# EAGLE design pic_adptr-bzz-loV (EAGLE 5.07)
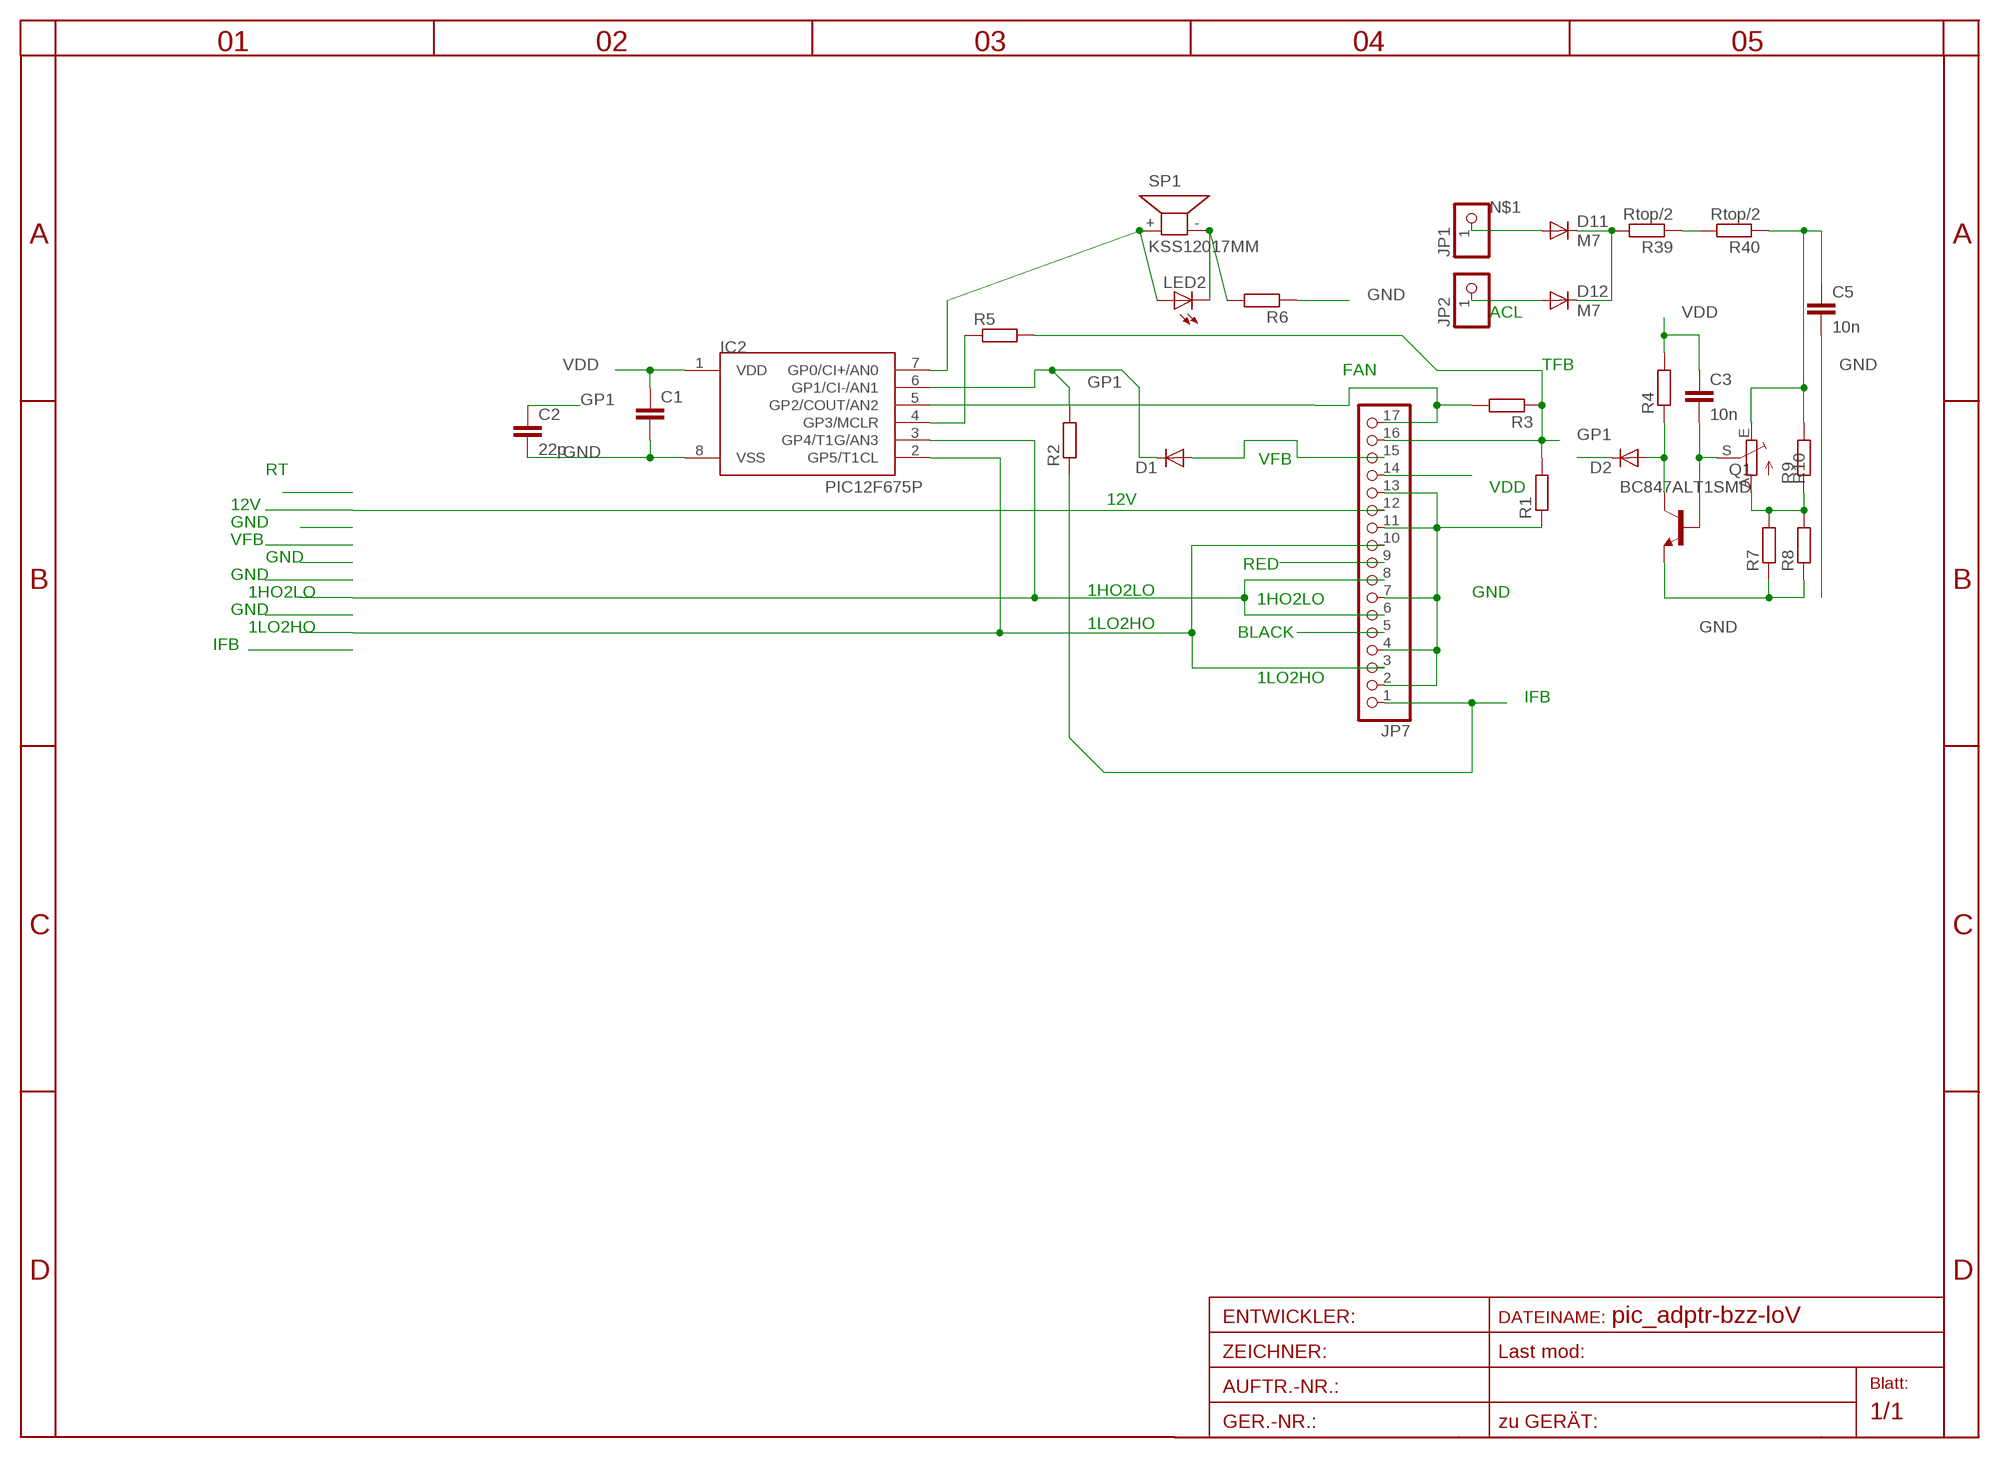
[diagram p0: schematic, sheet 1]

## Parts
C1  C-EUC1206  [C1206]
C2  22p  C-EUC0805  [C0805]
C3  10n  C-EUC0805  [C0805]
C5  10n  C-EUC1206  [C1206]
D1  DIODE-MINIMELF  [MINIMELF]
D2  DIODE-MINIMELF  [MINIMELF]
D11  M7  DIODE-SMA-DO214  [SMA-DO214AC]
D12  M7  DIODE-SMA-DO214  [SMA-DO214AC]
IC2  PIC12F675P  [DIL8]
JP1  PINHD-1X11X0.4  [1X01]
JP2  PINHD-1X11X0.4  [1X01]
JP7  PINHD-1X17  [1X17]
LED2  LEDCHIPLED_1206  [CHIPLED_1206]
Q1  BC847ALT1SMD  [SOT23]
R1  R-EU_R1206  [R1206]
R2  R-EU_R0805  [R0805]
R3  R-EU_R0805  [R0805]
R4  R-EU_R1206  [R1206]
R5  R-EU_R0805  [R0805]
R6  R-EU_R0805  [R0805]
R7  R-EU_R0805  [R0805]
R8  R-EU_R0805  [R0805]
R9  R-EU_R1206  [R1206]
R10  TRIM_EU-B64Y  [B64Y]
R39  Rtop/2  R-EU_R1206  [R1206]
R40  Rtop/2  R-EU_R1206  [R1206]
SP1  KSS12017MM  [KSS1202]

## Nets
1HO2LO: IC2.3(GP4/T1G/AN3) JP7.6 JP7.8
1LO2HO: IC2.2(GP5/T1CL) JP7.3 JP7.10
12V: JP7.12
ACL: D12.A JP2.1
BLACK: JP7.5
FAN: IC2.5(GP2/COUT/AN2) JP7.17 R3.2
GND: C1.2 C2.2 C5.2 IC2.8(VSS) JP7.2 JP7.4 JP7.7 JP7.11 JP7.13 Q1.2(E) R1.1 R6.1 R7.1 R8.1
GP1: C2.1 D1.C D2.C IC2.6(GP1/CI-/AN1) R2.2
IFB: JP7.1 R2.1
N$1: D11.A JP1.1
N$2: D11.K(C) D12.K(C) R39.2
N$3: IC2.4(GP3/MCLR) R5.1
N$4: IC2.7(GP0/CI+/AN0) LED2.A SP1.+
N$5: LED2.C R6.2 SP1.-
N$6: R39.1 R40.2
N$7: D2.A Q1.3(C) R4.1
N$12: R7.2 R8.2 R9.1 R10.A
N$13: C3.2 Q1.1(B) R10.S
N$19: C5.1 R9.2 R10.E R40.1
RED: JP7.9
TFB: JP7.16 R1.2 R3.1 R5.2
VDD: C1.1 C3.1 IC2.1(VDD) JP7.14 R4.2
VFB: D1.A JP7.15

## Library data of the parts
C1-C3 C5 = rcl:C-EU: CAPACITOR, European symbol
D1 D2 D11 D12 = diode:DIODE-: DIODE
IC2 = microchip-5:PIC12F6*: uPC nW 1k Program Flash memory 2x Timer Comparator 10b A/D converter/ 4xIN
JP1 JP2 = pinhead:PINHD-1X1: PIN HEADER
JP7 = pinhead:PINHD-1X17: PIN HEADER
LED2 = led:LED: LED
Q1 = transistor-npn:BC847*: NPN Transistor
R1-R9 = rcl:R-EU_: RESISTOR, European symbol
R10 = pot:TRIM_EU-: POTENTIOMETER
R39 R40 = rcl-2:R-EU_: RESISTOR, European symbol
SP1 = buzzer:KSS1201: SPEAKER

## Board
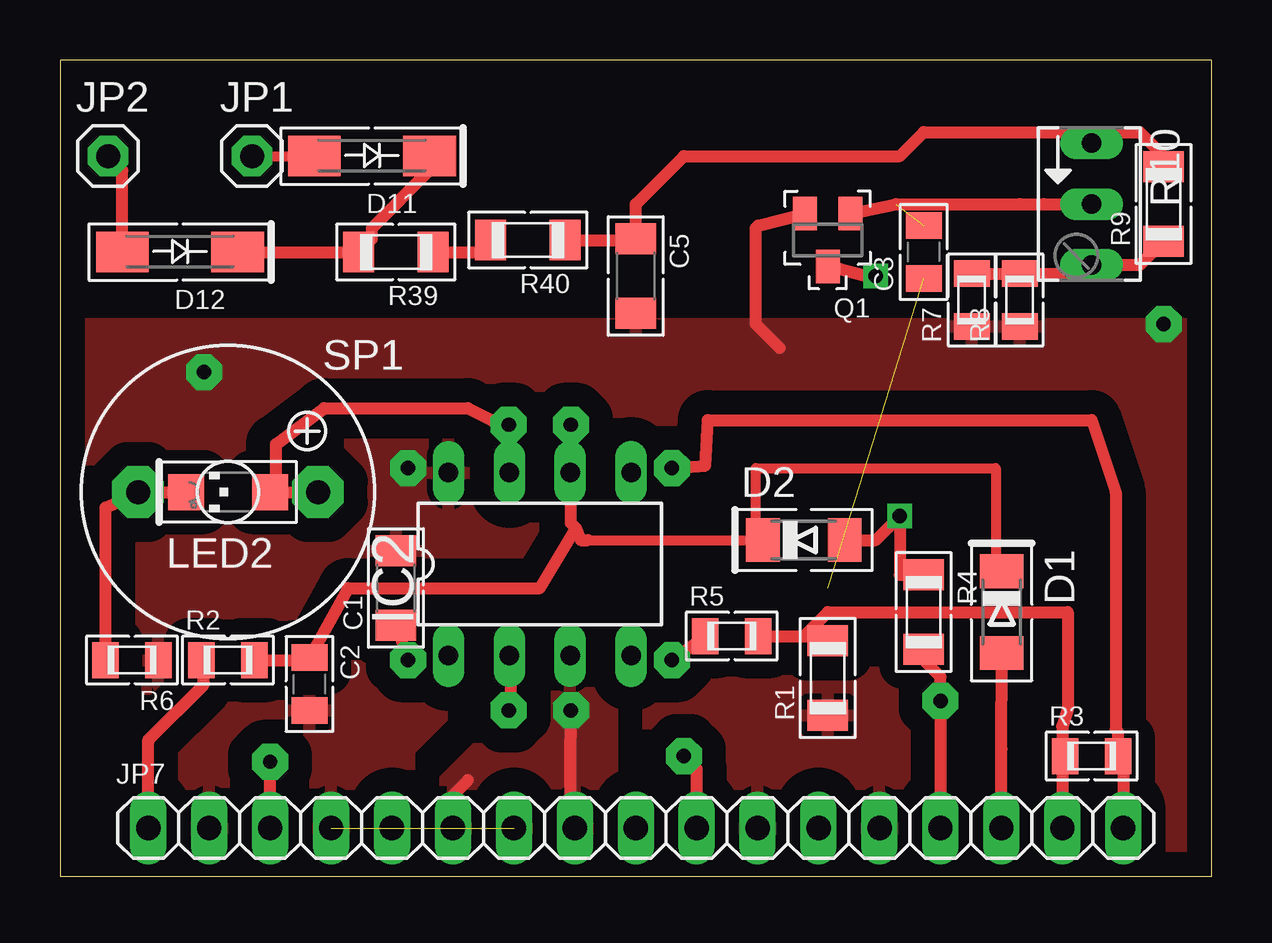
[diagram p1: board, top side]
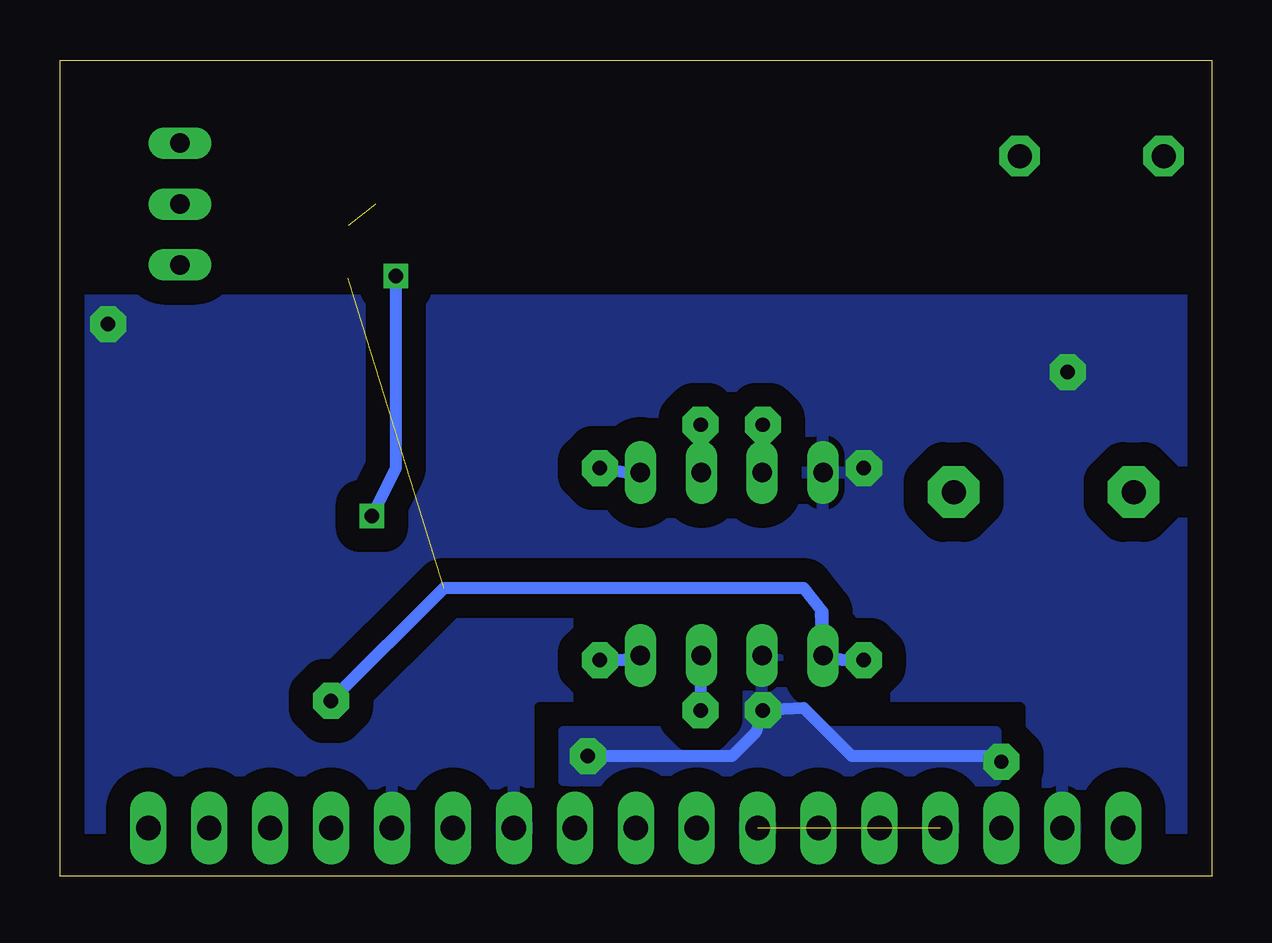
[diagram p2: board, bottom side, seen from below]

Size 48 x 34 mm. Coordinates in mm from the lower left corner, seen from the top.
Outline: 0,0 48,0 48,34 0,34 0,0
Copper layers (1*16): Top 0.035mm / dielectric 1.5mm / Bottom 0.035mm
Design rules "default *": minimum track width 10mil, minimum drill 20mil, track to track 8mil, track to pad 8mil, pad to pad 8mil, via to via 8mil, smd to smd 8mil, copper to edge 40mil, drill to drill 8mil, minimum pad ring 10mil, minimum via ring 8mil, stop-mask expansion 4mil, vias tented up to drill 0mil, thermal gap 10mil

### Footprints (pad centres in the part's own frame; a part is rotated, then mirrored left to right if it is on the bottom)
C1206 = smd 1.3 x 1.7: 1 -1.55,0; 2 1.55,0
C0805 = smd 1.1 x 1.5: 1 -1.1,0; 2 1.1,0
MINIMELF = smd 1.4 x 1.8: A 1.7,0; C -1.7,0
SMA-DO214AC = smd 2.2 x 1.7: A 2.4,0; K -2.4,0
DIL8 = drill 0.8 long: 1 -3.81,-3.81; 2 -1.27,-3.81; 3 1.27,-3.81; 4 3.81,-3.81; 5 3.81,3.81; 6 1.27,3.81; 7 -1.27,3.81; 8 -3.81,3.81
1X01 = drill 1 pad 1.676 octagon: 1 0,0
1X17 = drill 1.016 long: 1 -20.32,0; 2 -17.78,0; 3 -15.24,0; 4 -12.7,0; 5 -10.16,0; 6 -7.62,0; 7 -5.08,0; 8 -2.54,0; 9 0,0; 10 2.54,0; 11 5.08,0; 12 7.62,0; 13 10.16,0; 14 12.7,0; 15 15.24,0; 16 17.78,0; 17 20.32,0
CHIPLED_1206 = smd 1.5 x 1.5: A 0,-1.75; C 0,1.75
SOT23 = smd 1 x 1.4: 1 -0.95,-1.1; 2 0.95,-1.1; 3 0,1.1
R1206 = smd 1.3 x 1.7: 1 -1.55,0; 2 1.55,0
R0805 = smd 1.1 x 1.5: 1 -1.1,0; 2 1.1,0
B64Y = drill 0.813 long: A 2.54,0; E -2.54,0; S 0,0
KSS1202 = drill 1 pad 2.159 octagon: + 3.75,0; - -3.75,0

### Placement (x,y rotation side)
C1  14,12 90 top
C2  10.4,8 270 top
C3  36,26 90 top
C5  24,25 270 top
D1  39.25,11 270 top
D2  31,14 0 top
D11  13,30 180 top
D12  5,26 180 top
IC2  20,13 0 top
JP1  8,30 0 top
JP2  2,30 0 top
JP7  24,2 0 top
LED2  7,16 90 top
Q1  32,26.5 180 top
R1  32,8.25 90 top
R2  7,9 0 top
R3  43,5 0 top
R4  36,11 270 top
R5  28,10 0 top
R6  3,9 180 top
R7  38,24 90 top
R8  40,24 90 top
R9  46,28 90 top
R10  43,28 270 top
R39  14,26 180 top
R40  19.5,26.5 180 top
SP1  7,16 0 top

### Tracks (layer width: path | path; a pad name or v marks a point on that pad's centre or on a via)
1HO2LO  (via drill 0.6 pad 1.5)
  Top 0.5: v21.3,6.9 21.27,2.19 JP7.8 | 17,4 16,3 16,2.38 JP7.6
  Bottom 0.5: v21.3,6.9 IC2.3
  pour Top (isolate 1, rank 2): 20,8 23,8 23,1 21,1 21,3 18,3 18,2 17,1 15,1 15,3
1LO2HO  (via drill 0.6 pad 1.5)
  Top 0.5: JP7.3 v8.76,4.76 | JP7.10 26.54,4.46 v26,5 | v18.7,6.9 18.8,7.6 18.8,9.1
  Bottom 0.5: v8.76,4.76 9,5 15,5 16,6 17,7 v18.7,6.9 19,6 20,5 v26,5 | IC2.2 19,8.92 IC2.2
  pour Bottom (isolate 1): 19,9 20,8 20,7 21,6 27,6 27,4 9,4 9,6 16,6 17,7 17,8 18,9
ACL
  Top 0.5: D12.A 2.6,29.4 JP2.1
FAN  (via drill 0.6 pad 1.5)
  Top 0.5: JP7.17 44.32,4.78 R3.2 44.1,6 44,6.1 44,16 43,19 27,19 26.9,17.1 v25.5,17
  Bottom 0.5: IC2.5 24.41,16.81 v25.5,17
GND  (via drill 0.6 pad 1.5)  (1 unrouted)
  Top 0.5: Q1.2 29.1,27.1 29,27 29,23 30,22
  other vias: 46,23 14.5,17 6,21
  pour Top (isolate 1, rank 3): 47,23 1,23 1,1 47,1
  pour Bottom (isolate 1, rank 3): 47,24 1,24 1,2 47,2
GP1  (via drill 0.6 pad 1.5)
  Top 0.406: D1.C 39,12.7 39,17 29,17 29,14 D2.C 22,14
  Top 0.5: 22,14 21.7,14 21.5,14.5 | 21.5,14.5 20,12 12,12 C2.1 10.3,9 R2.2 | v21.3,18.8 21.3,16.3 21.3,14.7 21.5,14.5
  Bottom 0.5: IC2.6 21.27,18.77 v21.3,18.8
IFB
  Top 0.5: JP7.1 3.68,5.58 3.68,5.68 6,8 R2.1
N$1
  Top 0.406: JP1.1 D11.A
N$2
  Top 0.5: D11.K 15.4,29.4 13,27 13,26.55 R39.2 D12.K
N$3  (via drill 0.6 pad 1.5)
  Top 0.5: v25.5,9 R5.1
  Bottom 0.5: v25.5,9 24.52,9 IC2.4
N$4  (via drill 0.6 pad 1.5)
  Top 0.5: v18.7,18.8 18.2,18.8 18,19 17,19.5 11,19.5 9,18 9,16.25 LED2.A SP1.+
  Bottom 0.5: IC2.7 18.73,18.77 v18.7,18.8
N$5
  Top 0.5: LED2.C SP1.- 1.9,15.35 R6.2
N$6
  Top 0.5: R39.1 17.45,26 R40.2
N$7  (via drill 0.6)
  Top 0.5: Q1.3 33.9,24.9 v34,25 | R4.1 35,12.55 v35,15 34,14 D2.A
  Bottom 0.5: v34,25 34,17 v35,15
N$12
  Top 0.5: R7.2 R8.2 42.64,25.1 R10.A 45.01,25.46 R9.1
N$13  (1 unrouted)
  Top 0.5: R10.S 41,28 40,28 34.85,28 Q1.1
N$19
  Top 0.5: R40.1 23.95,26.5 C5.1 24,28 26,30 35,30 36,31 42.54,31 R10.E 43.46,31 45,31 46,30 R9.2
TFB
  Top 0.5: 41.78,4.88 JP7.16 | 41.78,4.88 R3.1 | 41.78,4.88 41.78,6.22 42,7 42,11 32,11 31,10 | 31,10 31.8,10 R1.2 | R5.2 31,10
VDD  (via drill 0.6 pad 1.5)  (1 unrouted)
  Top 0.5: JP7.14 v36.7,7.3 36.7,8.3 36,9 R4.2 | C1.1 v14.5,9
  Bottom 0.5: v36.7,7.3 32,12 17,12 16.2,11 16.2,9.48 IC2.1 | IC2.1 16.28,11 | v14.5,9 15.38,9 IC2.1
VFB
  Top 0.5: JP7.15 39.24,5.29 D1.A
